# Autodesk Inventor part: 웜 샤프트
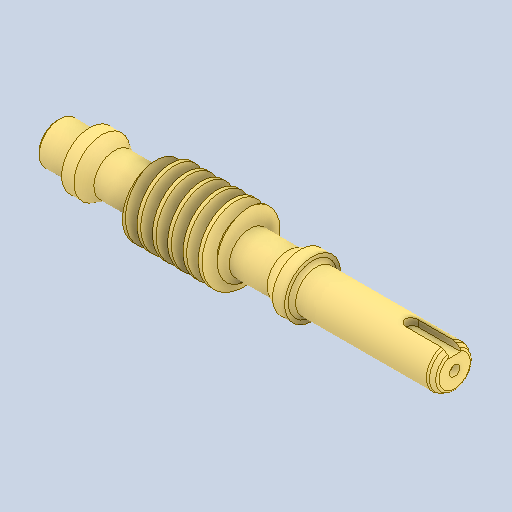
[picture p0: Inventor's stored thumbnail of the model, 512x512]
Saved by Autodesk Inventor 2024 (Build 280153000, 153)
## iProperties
Created: 2026-01
Part Number: 웜 샤프트
Material: 강철, 합금
Document SubType Name: Modeling
Designer: 2-10
Density: 7.73 g/cm^3
Appearance: 기본값
Author: jhkim
Sending System: Autodesk Inventor 2026
Preprocessor: ST-DEVELOPER v20.1
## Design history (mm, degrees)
node "웜 샤프트1"
node "솔리드2"
node "솔리드1"
